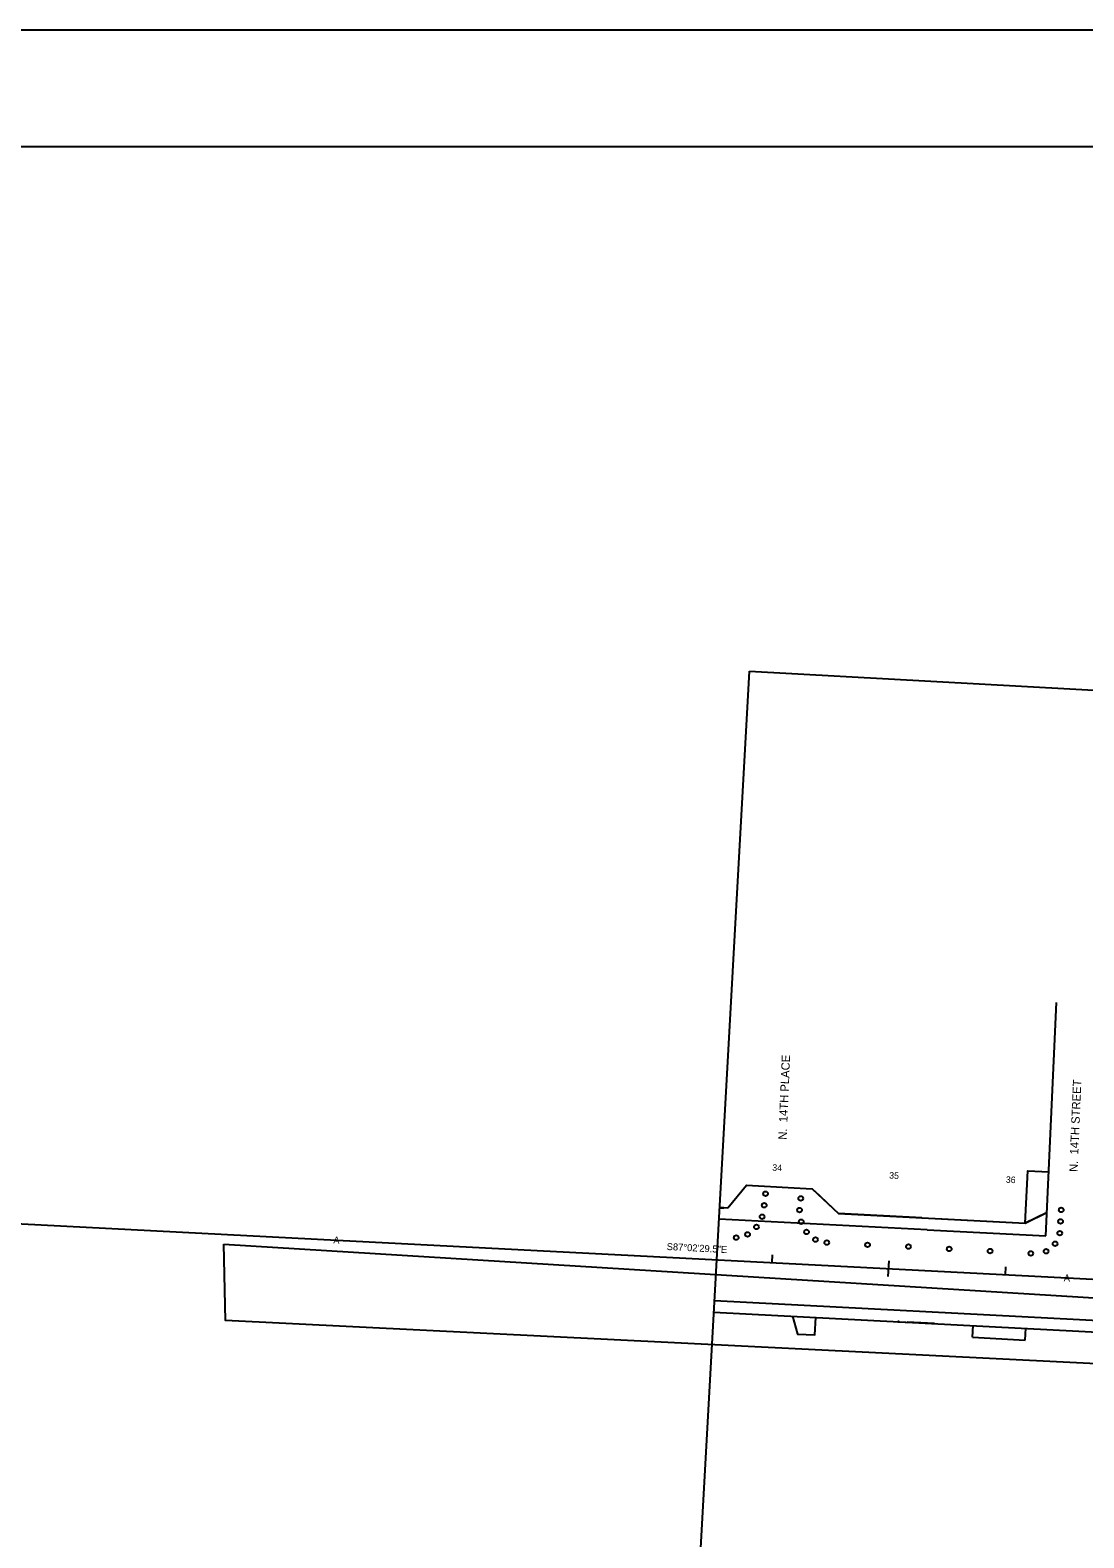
# Model space of a CAD drawing. Extents: x 679444 to 687671, y 733868 to 736107.
# Drawn here: x 682042 to 682944, y 734816 to 736107 of the extents above; entities that cross this region are included whole.
import ezdxf

# ---------------------------------------------------------------- set-up
doc = ezdxf.new("R2010")
doc.units = 0
for name, color, linetype in [('$', 7, 'Continuous'), ('090338 Base_ROW 3 - R_Horz Alg', 7, 'Continuous'), ('border All Plan 20-40_Border 3 - Level 1', 7, 'Continuous'), ('C-TOPO', 7, 'Continuous'), ('C-TOPO-FEAT', 7, 'Continuous'), ('Clipping Boundary', 7, 'Continuous'), ('MOT Stage 1', 7, 'Continuous'), ('MOT Stage 1b', 7, 'Continuous'), ('MOT Stage 1c', 7, 'Continuous'), ('R_Horz Alg', 7, 'Continuous'), ('R_Horz Alg Station', 7, 'Continuous'), ('R_TYPE_A_CURB', 7, 'Continuous'), ('RW-EX', 7, 'Continuous'), ('RW-PR', 7, 'Continuous'), ('V-NODE', 7, 'Continuous')]:
    doc.layers.add(name, color=color, linetype=linetype)

# ---------------------------------------------------------------- blocks, each defined once
blk = doc.blocks.new('BAREL_1631')
at = {"layer": 'MOT Stage 1'}
blk.add_circle((0, 0), 2.88, dxfattribs=at)
blk = doc.blocks.new('BAREL_1632')
at = {"layer": 'MOT Stage 1'}
blk.add_circle((0, 0), 2.88, dxfattribs=at)
blk = doc.blocks.new('BAREL_1633')
at = {"layer": 'MOT Stage 1'}
blk.add_circle((0, 0), 2.88, dxfattribs=at)
blk = doc.blocks.new('BAREL_1634')
at = {"layer": 'MOT Stage 1'}
blk.add_circle((0, 0), 2.88, dxfattribs=at)
blk = doc.blocks.new('BAREL_1635')
at = {"layer": 'MOT Stage 1'}
blk.add_circle((0, 0), 2.88, dxfattribs=at)
blk = doc.blocks.new('BAREL_1641')
at = {"layer": 'MOT Stage 1'}
blk.add_circle((0, 0), 2.88, dxfattribs=at)
blk = doc.blocks.new('BAREL_1642')
at = {"layer": 'MOT Stage 1'}
blk.add_circle((0, 0), 2.88, dxfattribs=at)
blk = doc.blocks.new('BAREL_1643')
at = {"layer": 'MOT Stage 1'}
blk.add_circle((0, 0), 2.88, dxfattribs=at)
blk = doc.blocks.new('BAREL_1644')
at = {"layer": 'MOT Stage 1'}
blk.add_circle((0, 0), 2.88, dxfattribs=at)
blk = doc.blocks.new('BAREL_1645')
at = {"layer": 'MOT Stage 1'}
blk.add_circle((0, 0), 2.88, dxfattribs=at)
blk = doc.blocks.new('BAREL_1646')
at = {"layer": 'MOT Stage 1'}
blk.add_circle((0, 0), 2.88, dxfattribs=at)
blk = doc.blocks.new('BAREL_1647')
at = {"layer": 'MOT Stage 1'}
blk.add_circle((0, 0), 2.88, dxfattribs=at)
blk = doc.blocks.new('BAREL_1648')
at = {"layer": 'MOT Stage 1'}
blk.add_circle((0, 0), 2.88, dxfattribs=at)
blk = doc.blocks.new('BAREL_1649')
at = {"layer": 'MOT Stage 1'}
blk.add_circle((0, 0), 2.88, dxfattribs=at)
blk = doc.blocks.new('BAREL_1650')
at = {"layer": 'MOT Stage 1'}
blk.add_circle((0, 0), 2.88, dxfattribs=at)
blk = doc.blocks.new('BAREL_1651')
at = {"layer": 'MOT Stage 1'}
blk.add_circle((0, 0), 2.88, dxfattribs=at)
blk = doc.blocks.new('BAREL_1659')
at = {"layer": 'MOT Stage 1'}
blk.add_circle((0, 0), 2.88, dxfattribs=at)
blk = doc.blocks.new('BAREL_1660')
at = {"layer": 'MOT Stage 1'}
blk.add_circle((0, 0), 2.88, dxfattribs=at)
blk = doc.blocks.new('BAREL_1661')
at = {"layer": 'MOT Stage 1'}
blk.add_circle((0, 0), 2.88, dxfattribs=at)
blk = doc.blocks.new('BAREL_1662')
at = {"layer": 'MOT Stage 1'}
blk.add_circle((0, 0), 2.88, dxfattribs=at)
blk = doc.blocks.new('BAREL_1663')
at = {"layer": 'MOT Stage 1'}
blk.add_circle((0, 0), 2.88, dxfattribs=at)
blk = doc.blocks.new('BAREL_1664')
at = {"layer": 'MOT Stage 1'}
blk.add_circle((0, 0), 2.88, dxfattribs=at)
blk = doc.blocks.new('BAREL_1744')
at = {"layer": 'MOT Stage 1b'}
blk.add_circle((0, 0), 2.88, dxfattribs=at)
blk = doc.blocks.new('BAREL_1745')
at = {"layer": 'MOT Stage 1b'}
blk.add_circle((0, 0), 2.88, dxfattribs=at)
blk = doc.blocks.new('BAREL_1746')
at = {"layer": 'MOT Stage 1b'}
blk.add_circle((0, 0), 2.88, dxfattribs=at)
blk = doc.blocks.new('BAREL_1747')
at = {"layer": 'MOT Stage 1b'}
blk.add_circle((0, 0), 2.88, dxfattribs=at)
blk = doc.blocks.new('BAREL_1748')
at = {"layer": 'MOT Stage 1b'}
blk.add_circle((0, 0), 2.88, dxfattribs=at)
blk = doc.blocks.new('BAREL_1749')
at = {"layer": 'MOT Stage 1b'}
blk.add_circle((0, 0), 2.88, dxfattribs=at)
blk = doc.blocks.new('BAREL_1750')
at = {"layer": 'MOT Stage 1b'}
blk.add_circle((0, 0), 2.88, dxfattribs=at)
blk = doc.blocks.new('BAREL_1751')
at = {"layer": 'MOT Stage 1b'}
blk.add_circle((0, 0), 2.88, dxfattribs=at)
blk = doc.blocks.new('BAREL_1752')
at = {"layer": 'MOT Stage 1b'}
blk.add_circle((0, 0), 2.88, dxfattribs=at)
blk = doc.blocks.new('BAREL_1753')
at = {"layer": 'MOT Stage 1b'}
blk.add_circle((0, 0), 2.88, dxfattribs=at)
blk = doc.blocks.new('BAREL_1754')
at = {"layer": 'MOT Stage 1b'}
blk.add_circle((0, 0), 2.88, dxfattribs=at)
blk = doc.blocks.new('BAREL_1755')
at = {"layer": 'MOT Stage 1b'}
blk.add_circle((0, 0), 2.88, dxfattribs=at)
blk = doc.blocks.new('BAREL_1756')
at = {"layer": 'MOT Stage 1b'}
blk.add_circle((0, 0), 2.88, dxfattribs=at)
blk = doc.blocks.new('BAREL_1757')
at = {"layer": 'MOT Stage 1b'}
blk.add_circle((0, 0), 2.88, dxfattribs=at)
blk = doc.blocks.new('BAREL_1758')
at = {"layer": 'MOT Stage 1c'}
blk.add_circle((0, 0), 2.88, dxfattribs=at)
blk = doc.blocks.new('BAREL_1759')
at = {"layer": 'MOT Stage 1c'}
blk.add_circle((0, 0), 2.88, dxfattribs=at)
blk = doc.blocks.new('BAREL_1760')
at = {"layer": 'MOT Stage 1c'}
blk.add_circle((0, 0), 2.88, dxfattribs=at)
blk = doc.blocks.new('BAREL_1761')
at = {"layer": 'MOT Stage 1c'}
blk.add_circle((0, 0), 2.88, dxfattribs=at)
blk = doc.blocks.new('BAREL_1762')
at = {"layer": 'MOT Stage 1c'}
blk.add_circle((0, 0), 2.88, dxfattribs=at)
blk = doc.blocks.new('BAREL_1763')
at = {"layer": 'MOT Stage 1c'}
blk.add_circle((0, 0), 2.88, dxfattribs=at)
blk = doc.blocks.new('BAREL_1764')
at = {"layer": 'MOT Stage 1c'}
blk.add_circle((0, 0), 2.88, dxfattribs=at)
blk = doc.blocks.new('BAREL_1765')
at = {"layer": 'MOT Stage 1c'}
blk.add_circle((0, 0), 2.88, dxfattribs=at)
blk = doc.blocks.new('BAREL_1766')
at = {"layer": 'MOT Stage 1c'}
blk.add_circle((0, 0), 2.88, dxfattribs=at)
blk = doc.blocks.new('BAREL_1767')
at = {"layer": 'MOT Stage 1c'}
blk.add_circle((0, 0), 2.88, dxfattribs=at)
blk = doc.blocks.new('BAREL_1768')
at = {"layer": 'MOT Stage 1c'}
blk.add_circle((0, 0), 2.88, dxfattribs=at)
blk = doc.blocks.new('BAREL_1769')
at = {"layer": 'MOT Stage 1c'}
blk.add_circle((0, 0), 2.88, dxfattribs=at)
blk = doc.blocks.new('BAREL_1770')
at = {"layer": 'MOT Stage 1c'}
blk.add_circle((0, 0), 2.88, dxfattribs=at)
blk = doc.blocks.new('BAREL_1771')
at = {"layer": 'MOT Stage 1c'}
blk.add_circle((0, 0), 2.88, dxfattribs=at)

msp = doc.modelspace()

# ---------------------------------------------------------------- linework, layer by layer
at = {"layer": '$'}
msp.add_lwpolyline([(679553.9, 733968.3), (687571.1, 733968.3), (687571.1, 736006.7), (679553.9, 736006.7), (679553.9, 733968.3)], dxfattribs=at)
at = {"layer": 'border All Plan 20-40_Border 3 - Level 1'}
for p, q in [((682601.3, 734532.1), (682658.2, 735557.9)), ((682658.2, 735557.9), (684236.6, 735470.4))]:
    msp.add_line(p, q, dxfattribs=at)
at = {"layer": 'C-TOPO'}
msp.add_lwpolyline([(679453.9, 733868.3), (687671.1, 733868.3), (687671.1, 736106.7), (679453.9, 736106.7), (679453.9, 733868.3)], dxfattribs=at)
at = {"layer": 'C-TOPO-FEAT'}
msp.add_lwpolyline([(679553.9, 733968.3), (687571.1, 733968.3), (687571.1, 736006.7), (679553.9, 736006.7), (679553.9, 733968.3)], dxfattribs=at)
at = {"layer": 'Clipping Boundary'}
msp.add_lwpolyline([(682208.3, 735067.1), (683203, 735005.7), (683576.8, 734982.6), (683585.6, 734947.8), (683582.6, 734838), (683533.7, 734842.8), (683477.6, 734938.7), (682209.6, 735001.8)], close=True, dxfattribs=at)
at = {"layer": 'R_Horz Alg Station'}
for p, q in [((680979.5, 735139), (682305, 735070.5)), ((682305, 735070.5), (682930.3, 735038.2)), ((682930.3, 735038.2), (683438.6, 735011.9))]:
    msp.add_line(p, q, dxfattribs=at)
for points in [[(682677.6, 735057.9), (682677.3, 735051.3)], [(682777.5, 735052.8), (682776.8, 735039.4)], [(682877.4, 735047.6), (682877, 735040.9)]]:
    msp.add_lwpolyline(points, dxfattribs=at)
at = {"layer": 'R_TYPE_A_CURB'}
for p, q in [((682735, 735092.9), (682714.1, 735112.5)), ((682632.7, 735098.6), (682636.3, 735098.4)), ((682632.7, 735098.1), (682636.3, 735097.9)), ((682636.3, 735098.4), (682636.3, 735097.9)), ((682805.7, 735089.7), (682734.5, 735093.4)), ((682912.4, 735093.9), (682894.3, 735085.1)), ((682912.4, 735093.9), (682912.4, 735094.1)), ((682912.9, 735093.6), (682912.9, 735094.1)), ((682805.6, 735089.2), (682805.7, 735089.7)), ((682822.8, 735088.3), (682822.9, 735088.8)), ((682822.9, 735088.8), (682894.3, 735085.1)), ((682785.3, 735001.1), (682785.2, 735000.6)), ((682785.2, 735000.6), (682816.6, 734999)), ((682785.3, 735001.1), (682786.3, 735001.1)), ((682793.3, 735000.7), (682816.6, 734999.5)), ((682816.6, 734999), (682816.6, 734999.5))]:
    msp.add_line(p, q, dxfattribs=at)
at = {"layer": 'RW-EX'}
for p, q in [((682912, 735074.2), (682921.1, 735274)), ((682810.4, 735079.4), (682632.2, 735088.6)), ((682810.4, 735079.4), (682912, 735074.2)), ((682628.3, 735018.7), (682968.2, 735001.2))]:
    msp.add_line(p, q, dxfattribs=at)
at = {"layer": 'RW-PR'}
for p, q in [((682894.3, 735085.1), (682912.9, 735094.2)), ((682627.7, 735008.8), (682967.7, 734991.2)), ((682849.2, 734987.3), (682849.7, 734997.3)), ((682849.2, 734987.3), (682894.2, 734985)), ((682894.2, 734985), (682894.7, 734995))]:
    msp.add_line(p, q, dxfattribs=at)
for points in [[(682894.3, 735085.1), (682896.6, 735130), (682914.5, 735129.1)], [(682639.7, 735098.3), (682655.7, 735117.5), (682711.9, 735114.6), (682734.5, 735093.4)], [(682632.7, 735098.6), (682639.7, 735098.3)], [(682734.5, 735093.4), (682894.3, 735085.1)], [(682694.9, 735005.3), (682699.2, 734990.1), (682714.1, 734989.3), (682714.9, 735004.3)]]:
    msp.add_lwpolyline(points, dxfattribs=at)
at = {"layer": 'V-NODE'}
msp.add_lwpolyline([(679553.9, 733968.3), (687571.1, 733968.3), (687571.1, 736006.7), (679553.9, 736006.7), (679553.9, 733968.3)], dxfattribs=at)

# ---------------------------------------------------------------- block references
at = {"layer": 'MOT Stage 1'}
for name, p, xscale, yscale, rotation in [('BAREL_1641', (682672, 735110.3), 0.6945420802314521, 0.6945420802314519, 87.04179557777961), ('BAREL_1646', (682702.1, 735106.2), 0.6945420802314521, 0.6945420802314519, 87.04179557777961), ('BAREL_1643', (682669, 735090.6), 0.6945420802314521, 0.6945420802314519, 87.04179557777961), ('BAREL_1642', (682670.9, 735100.4), 0.6945420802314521, 0.6945420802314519, 87.04179557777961), ('BAREL_1647', (682701.1, 735096.3), 0.6945420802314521, 0.6945420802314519, 87.04179557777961), ('BAREL_1631', (682925.1, 735096.4), 0.6945420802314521, 0.6945420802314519, 87.04179557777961), ('BAREL_1645', (682656.6, 735075.4), 0.6945420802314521, 0.6945420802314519, 87.04179557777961), ('BAREL_1644', (682664.2, 735081.8), 0.6945420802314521, 0.6945420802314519, 87.04179557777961), ('BAREL_1648', (682702.5, 735086.3), 0.6945420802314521, 0.6945420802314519, 87.04179557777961), ('BAREL_1649', (682707.1, 735077.5), 0.6945420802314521, 0.6945420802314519, 87.04179557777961), ('BAREL_1633', (682923.9, 735076.5), 0.6945420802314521, 0.6945420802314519, 87.04179557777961), ('BAREL_1632', (682924.6, 735086.5), 0.6945420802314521, 0.6945420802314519, 87.04179557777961), ('BAREL_1659', (682646.9, 735072.7), 0.6945420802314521, 0.6945420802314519, 87.04179557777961), ('BAREL_1650', (682714.7, 735071), 0.6945420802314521, 0.6945420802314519, 87.04179557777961), ('BAREL_1651', (682724.4, 735068.4), 0.6945420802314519, 0.6945420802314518, 102.77338179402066), ('BAREL_1660', (682759.3, 735066.5), 0.6945420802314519, 0.6945420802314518, 102.77338179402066), ('BAREL_1661', (682794.3, 735065), 0.6945420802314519, 0.6945420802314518, 102.77338179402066), ('BAREL_1662', (682829.2, 735063), 0.6945420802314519, 0.6945420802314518, 102.77338179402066), ('BAREL_1634', (682919.8, 735067.4), 0.6945420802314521, 0.6945420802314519, 87.04179557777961), ('BAREL_1663', (682864.2, 735061.1), 0.6945420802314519, 0.6945420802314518, 102.77338179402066), ('BAREL_1664', (682899.1, 735059.2), 0.6945420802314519, 0.6945420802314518, 102.77338179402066), ('BAREL_1635', (682912.1, 735061), 0.6945420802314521, 0.6945420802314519, 87.04179557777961)]:
    msp.add_blockref(name, p, dxfattribs=dict(at, xscale=xscale, yscale=yscale, rotation=rotation))
at = {"layer": 'MOT Stage 1b'}
for name, p, xscale, yscale, rotation in [('BAREL_1749', (682672, 735110.3), 0.6945420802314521, 0.6945420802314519, 87.04179557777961), ('BAREL_1750', (682702.1, 735106.2), 0.6945420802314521, 0.6945420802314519, 87.04179557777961), ('BAREL_1747', (682669, 735090.6), 0.6945420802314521, 0.6945420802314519, 87.04179557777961), ('BAREL_1748', (682670.9, 735100.4), 0.6945420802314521, 0.6945420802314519, 87.04179557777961), ('BAREL_1751', (682701.1, 735096.3), 0.6945420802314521, 0.6945420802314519, 87.04179557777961), ('BAREL_1745', (682656.6, 735075.4), 0.6945420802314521, 0.6945420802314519, 87.04179557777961), ('BAREL_1746', (682664.2, 735081.8), 0.6945420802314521, 0.6945420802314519, 87.04179557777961), ('BAREL_1752', (682702.5, 735086.3), 0.6945420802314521, 0.6945420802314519, 87.04179557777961), ('BAREL_1753', (682707.1, 735077.5), 0.6945420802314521, 0.6945420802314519, 87.04179557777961), ('BAREL_1744', (682646.9, 735072.7), 0.6945420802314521, 0.6945420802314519, 87.04179557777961), ('BAREL_1755', (682714.7, 735071), 0.6945420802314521, 0.6945420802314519, 87.04179557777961), ('BAREL_1754', (682724.4, 735068.4), 0.6945420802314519, 0.6945420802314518, 102.77338179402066), ('BAREL_1756', (682759.3, 735066.5), 0.6945420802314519, 0.6945420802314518, 102.77338179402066), ('BAREL_1757', (682794.3, 735065), 0.6945420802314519, 0.6945420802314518, 102.77338179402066)]:
    msp.add_blockref(name, p, dxfattribs=dict(at, xscale=xscale, yscale=yscale, rotation=rotation))
at = {"layer": 'MOT Stage 1c'}
for name, p, xscale, yscale, rotation in [('BAREL_1768', (682672, 735110.3), 0.6945420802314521, 0.6945420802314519, 87.04179557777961), ('BAREL_1769', (682702.1, 735106.2), 0.6945420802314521, 0.6945420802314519, 87.04179557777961), ('BAREL_1766', (682669, 735090.6), 0.6945420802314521, 0.6945420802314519, 87.04179557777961), ('BAREL_1767', (682670.9, 735100.4), 0.6945420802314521, 0.6945420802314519, 87.04179557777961), ('BAREL_1770', (682701.1, 735096.3), 0.6945420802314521, 0.6945420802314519, 87.04179557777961), ('BAREL_1764', (682656.6, 735075.4), 0.6945420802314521, 0.6945420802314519, 87.04179557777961), ('BAREL_1765', (682664.2, 735081.8), 0.6945420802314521, 0.6945420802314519, 87.04179557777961), ('BAREL_1771', (682702.5, 735086.3), 0.6945420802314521, 0.6945420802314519, 87.04179557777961), ('BAREL_1762', (682707.1, 735077.5), 0.6945420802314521, 0.6945420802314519, 87.04179557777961), ('BAREL_1763', (682646.9, 735072.7), 0.6945420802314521, 0.6945420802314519, 87.04179557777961), ('BAREL_1761', (682714.7, 735071), 0.6945420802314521, 0.6945420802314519, 87.04179557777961), ('BAREL_1760', (682724.4, 735068.4), 0.6945420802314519, 0.6945420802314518, 102.77338179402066), ('BAREL_1759', (682759.3, 735066.5), 0.6945420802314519, 0.6945420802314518, 102.77338179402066), ('BAREL_1758', (682794.3, 735065), 0.6945420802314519, 0.6945420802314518, 102.77338179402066)]:
    msp.add_blockref(name, p, dxfattribs=dict(at, xscale=xscale, yscale=yscale, rotation=rotation))

# ---------------------------------------------------------------- texts
at = {"layer": '$'}
for s, height, rotation, p in [('N.  14TH PLACE', 7.2, 87.5995, (682690, 735156.4)), ('N.  14TH STREET', 7.2, 87.5995, (682939.1, 735128.8)), ('34', 5.6, 357.0415, (682677.6, 735130)), ('35', 5.6, 357.0415, (682777.7, 735123.3)), ('36', 5.6, 357.0415, (682877.6, 735119.7))]:
    msp.add_text(s, height=height, rotation=rotation, dxfattribs=at).set_placement(p)
at = {"layer": '090338 Base_ROW 3 - R_Horz Alg'}
msp.add_text('A', height=2.4, rotation=357.0415, dxfattribs=at).set_placement((682929.1, 735037))
at = {"layer": 'R_Horz Alg'}
for p in [(682301.8, 735067.7), (682927.2, 735035.3)]:
    msp.add_text('A', height=6, rotation=357.0415, dxfattribs=at).set_placement(p)
at = {"layer": 'R_Horz Alg Station'}
msp.add_text('S87%%d02\'29.5"E', height=6, rotation=357.0415, dxfattribs=at).set_placement((682587.2, 735062.1))

doc.saveas('drawing.dxf')
